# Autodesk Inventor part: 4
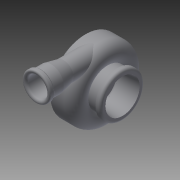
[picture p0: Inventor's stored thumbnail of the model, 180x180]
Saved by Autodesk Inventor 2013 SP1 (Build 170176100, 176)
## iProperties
Created: 2013-05
Part Number: 4
Material: Titanium
Document SubType Name: Modeling
Designer: 50384
Density: 1 g/cm^3
Author: 50384
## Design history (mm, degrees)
sketch "Sketch1"
  geometry: L1 (0, 0)-(0, 55); L2 (0, 55)-(-5, 55); L3 (-5, 55)-(-5, 38); L4 (-5, 38)-(-10, 38); L5 (-10, 38)-(-10, 64.6); L6 (-10, 64.6)-(-28.44, 64.6); L7 (0, 55)-(0, 66.6); L8 (-3, 69.6)-(-28.98, 69.6); L9 (-44.76, 38)-(-58.76, 38); L10 (-63.76, 43)-(-68.76, 43); L11 (-68.76, 43)-(-68.76, 38); L12 (-73.76, 38)-(-73.76, 33.552); L13 (-37.97, 38)-(-26.241, 38); L14 (-28.46, 64.6)-(-10, 64.6); L15 (-10, 64.6)-(-10, 38); L16 (-10, 38)-(-5, 38); L17 (-5, 38)-(-5, 55); L18 (-5, 55)-(0, 55); L19 (0, 0)-(-35.86, 0); A1 r 15 centre (-28.46, 49.6) between (-28.46, 64.6) and (-37.97, 38); A2 r 20.007 centre (-28.46, 49.6) between (-27.939, 69.6) and (-44.76, 38); A3 r 3 centre (-3, 66.6) between (0, 66.6) and (-3, 69.6); A4 r 5 centre (-58.76, 43) between (-63.76, 43) and (-58.76, 38); A5 r 5 centre (-68.76, 38) between (-68.76, 43) and (-73.76, 38); A6 r 145 centre (-46.95, 176.052) between (-73.76, 33.552) and (-33.506, 31.677); A7 r 10.312 centre (-35.86, 41.716) between (-46.034, 40.04) and (-45.479, 38); A8 r 10.312 centre (-35.86, 41.716) between (-33.506, 31.677) and (-26.241, 38); 1 further point
  constraints: 38 end point, 18 point on circle, 8 centre point, 8 perpendicular, 5 parallel, 4 point on line, 4 tangent, 2 coincident, 2 collinear, 1 vertical
  dimensions: "d1" = 55 distance of L1.start L1.end; "d2" = 5 distance of L1.end L2.end; "d3" = 17 distance of L2.end L3.end; "d4" = 5 distance of L3.end L4.end; "d5" = 26.6 distance of L4.end L5.end; "d7" = 18.44 distance of L5.end L6.end; "d10" = 14.6 distance of L1.end point (0, 69.6); "d11" = 28.98 distance of point (0, 69.6) L8.end; "d12" = 3 radius of A3; "d13" = 14 distance of L9.start L9.end; "d15" = 5 distance of L10.start L10.end; "d18" = 290 diameter of A6
revolve "Revolution1" sketch "Sketch1" stored, may be unused: angle "d19" = 90 deg
workplane "Work Plane1"
sketch "Sketch3"
  geometry: L1 (0, 66.6)-(0, -66.6) reference; L2 (63.76, 43)-(63.76, -43) reference; L3 (0, 0)-(24.13, 0); L4 (24.13, 0)-(24.13, -49.81); C1 r 27.5 at (24.13, -49.81)
  constraints: 4 end point, 2 perpendicular, 1 centre point, 1 coincident
  dimensions: "d21" = 24.13 distance of L3.start L3.end; "d22" = 49.81 distance of L3.end L4.end; "d23" = 55 diameter of C1
workplane "Work Plane2"
sketch "Sketch4"
  geometry: L1 (0, 0)-(49.81, 0); L2 (49.81, 0)-(49.81, 120); L3 (49.81, 120)-(25.31, 120); L4 (22.31, 117)-(22.31, 112.96); L5 (25.31, 109.96)-(25.31, 89.96); L6 (30.52, 65.6)-(25.31, 89.96); L7 (30.52, 65.6)-(35.52, 65.6); L8 (35.52, 65.6)-(30.319, 89.918); L9 (30.319, 89.918)-(30.31, 115.002); C1 r 69.607 at (0, 0) reference; A1 r 5 centre (25.31, 115) between (30.31, 115.002) and (25.31, 120); A2 r 3 centre (25.31, 112.96) between (22.31, 112.96) and (25.31, 109.96); A3 r 3 centre (25.31, 117) between (25.31, 120) and (22.31, 117); 1 further point
  constraints: 18 end point, 6 point on circle, 3 centre point, 3 perpendicular, 2 tangent, 1 horizontal, 1 parallel
  dimensions: "d25" = 49.81 distance of L1.start L1.end; "d26" = 120 distance of L1.end L2.end; "d30" = 4.04 distance of L4.start L4.end; "d32" = 20 distance of L5.start L5.end; "d35" = 5 distance of L6.start L7.end
revolve "Revolution2" sketch "Sketch4" stored, may be unused: angle "d36" = 90 deg
sketch "Sketch5"
  geometry: C1 r 19.29 at (0, 0) reference; C2 r 14.29 at (0, 0) reference; 1 further point
extrude "Extrusion1" join sketch "Sketch5" stored distance "d37" = 25.4; taper "d38" = 0 deg
extrude "Extrusion2" cut sketch "Sketch5" distance "d39" = 52.07; taper "d40" = 0 deg
sketch "Sketch6"
  geometry: C1 r 3.4 at (0, 60); C2 r 3.4 at (-51.962, 30); C3 r 3.4 at (-51.962, -30); C4 r 3.4 at (0, -60); C5 r 3.4 at (51.962, -30); C6 r 3.4 at (51.962, 30)
  constraints: 6 centre point
  dimensions: "d43" = 6.8 diameter of C1
extrude "Extrusion3" cut sketch "Sketch6" stored distance "d47" = 52.07; taper "d48" = 0 deg
body "Solid1"
other parameters: "d24" = 24.13
